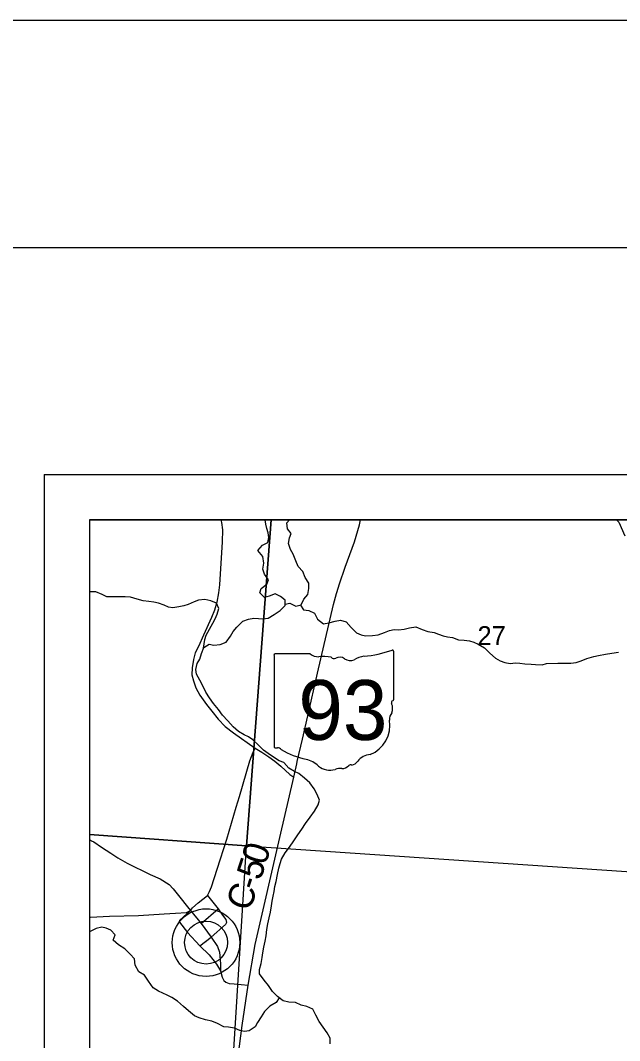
# Model space of a CAD drawing. Extents: x 0 to 34, y 0 to 22.
# Drawn here: x 1.948 to 3.268, y 19.753 to 22 of the extents above; entities that cross this region are included whole.
import ezdxf

# ---------------------------------------------------------------- set-up
doc = ezdxf.new("R2010")
doc.units = 0
for name, color, linetype in [('Default', 7, 'Continuous'), ('GM_X_County_Road', 7, 'Continuous'), ('GM_X_County_Road_Text', 7, 'Continuous'), ('GM_X_Minor_River', 7, 'Continuous'), ('GM_X_Section', 7, 'Continuous'), ('GM_X_Section_Text', 7, 'Continuous'), ('GM_X_State_Location', 7, 'Continuous'), ('GM_X_State_Route', 7, 'Continuous'), ('GM_X_State_Shield', 7, 'Continuous'), ('GM_X_Township_Road', 7, 'Continuous'), ('GM_X_Unincorporated', 7, 'Continuous'), ('GM_X_Unincorporated_Location', 7, 'Continuous'), ('SC_Scratch1', 7, 'Continuous'), ('SH_Border', 7, 'Continuous'), ('SH_Cut_Line', 7, 'Continuous'), ('SH_Data', 7, 'Continuous')]:
    doc.layers.add(name, color=color, linetype=linetype)

msp = doc.modelspace()

# ---------------------------------------------------------------- linework, layer by layer
at = {"layer": 'Default'}
for points in [[(2.4999, 20.9), (2.1, 20.9), (2.1, 20.207), (2.446, 20.1823)], [(3.5087, 20.9), (2.4999, 20.9), (2.446, 20.1823), (3.4572, 20.1141)], [(2.1, 20.207), (2.1, 19.197), (2.3543, 19.1806), (2.3838, 19.1776), (2.446, 20.1823)]]:
    msp.add_lwpolyline(points, close=True, dxfattribs=at)
at = {"layer": 'GM_X_County_Road'}
for points in [[(2.3895, 20.9), (2.391, 20.8942), (2.3933, 20.8785), (2.3924, 20.8516), (2.3866, 20.7573), (2.3841, 20.7398), (2.3804, 20.7189), (2.3751, 20.7012), (2.3689, 20.6848), (2.351, 20.6462), (2.3401, 20.6209), (2.3328, 20.6071), (2.3289, 20.593), (2.3261, 20.5744), (2.3254, 20.5592), (2.3291, 20.5454), (2.3342, 20.5305), (2.3431, 20.5144), (2.3576, 20.4937), (2.3694, 20.4787), (2.3832, 20.4615), (2.399, 20.4454), (2.4172, 20.4313), (2.4648, 20.3977), (2.48, 20.3885), (2.4952, 20.378), (2.5085, 20.3688), (2.5217, 20.3579), (2.5414, 20.3391), (2.5499, 20.3338)], [(3.2613, 20.9), (3.2658, 20.8947), (3.279, 20.8648)], [(2.3222, 20.0396), (2.3269, 20.0456), (2.3397, 20.0566), (2.3602, 20.073), (2.3645, 20.0814), (2.369, 20.0923), (2.3815, 20.1311), (2.4027, 20.1969), (2.423, 20.2677), (2.4305, 20.2911), (2.4536, 20.3697), (2.4605, 20.3887), (2.4648, 20.3977)], [(2.1, 20.025), (2.1023, 20.0253), (2.1444, 20.0271), (2.2081, 20.0292), (2.2649, 20.0327), (2.2893, 20.034), (2.3137, 20.0352), (2.3222, 20.0396), (2.3457, 20.0115), (2.3678, 19.9813), (2.3818, 19.9607), (2.3864, 19.9485), (2.3889, 19.9222), (2.3889, 19.9068), (2.3921, 19.8928), (2.3961, 19.8861), (2.4002, 19.882), (2.4076, 19.8795), (2.4186, 19.8785), (2.4499, 19.8758)]]:
    msp.add_lwpolyline(points, dxfattribs=at)
at = {"layer": 'GM_X_Minor_River'}
for points in [[(2.3518, 20.6193), (2.3639, 20.6262), (2.3738, 20.6243), (2.3878, 20.6255), (2.401, 20.6308), (2.4104, 20.6437), (2.4168, 20.654), (2.4244, 20.6639), (2.4379, 20.6772), (2.45, 20.6814), (2.4621, 20.6833), (2.472, 20.6829), (2.4822, 20.6822), (2.4939, 20.6838), (2.5072, 20.6914), (2.5204, 20.7009), (2.5313, 20.7112), (2.5309, 20.7233), (2.521, 20.7316), (2.5093, 20.7369), (2.4957, 20.7323), (2.4859, 20.7292), (2.4756, 20.7391), (2.4782, 20.7493), (2.4907, 20.7588), (2.4944, 20.7683), (2.4853, 20.7804), (2.4819, 20.7914), (2.4841, 20.8047), (2.4818, 20.8191), (2.4708, 20.8323), (2.4813, 20.8445), (2.493, 20.8506), (2.4949, 20.8612), (2.4933, 20.8714), (2.4907, 20.8813), (2.4887, 20.8908), (2.4869, 20.9)], [(2.5312, 20.7145), (2.5415, 20.7169), (2.5548, 20.7101), (2.5662, 20.7128), (2.5722, 20.7253), (2.5808, 20.7355), (2.5831, 20.7488), (2.583, 20.7606), (2.5754, 20.7731), (2.5697, 20.7863), (2.5594, 20.7973), (2.5549, 20.8102), (2.5484, 20.8246), (2.5427, 20.8352), (2.5381, 20.848), (2.5403, 20.8609), (2.5441, 20.8704), (2.5361, 20.8803), (2.5349, 20.8939), (2.5408, 20.9)], [(2.3512, 20.6175), (2.354, 20.6364), (2.3574, 20.6463), (2.3646, 20.6592), (2.3721, 20.6725), (2.377, 20.682), (2.3811, 20.6922), (2.3849, 20.7047), (2.3799, 20.7165), (2.3674, 20.7217), (2.3541, 20.7244), (2.3401, 20.7236), (2.3303, 20.7194), (2.3174, 20.714), (2.3076, 20.7106), (2.297, 20.7083), (2.2838, 20.7067), (2.2739, 20.7079), (2.2645, 20.712), (2.2523, 20.7165), (2.2417, 20.7188), (2.2311, 20.7206), (2.2182, 20.7221), (2.205, 20.7255), (2.1902, 20.7296), (2.1785, 20.7304), (2.1637, 20.7307), (2.1527, 20.7303), (2.1383, 20.7303), (2.1281, 20.7359), (2.1137, 20.742), (2.1001, 20.7419), (2.1, 20.7419)], [(2.5652, 20.7125), (2.5715, 20.7022), (2.5832, 20.7007), (2.5954, 20.6946), (2.6026, 20.6818), (2.6155, 20.6715), (2.6276, 20.6735), (2.6412, 20.6773), (2.6533, 20.6796), (2.6655, 20.6755), (2.6765, 20.6634), (2.6882, 20.6513), (2.6985, 20.6467), (2.7083, 20.6445), (2.7235, 20.6453), (2.736, 20.6472), (2.7496, 20.6522), (2.7609, 20.6567), (2.7711, 20.6587), (2.781, 20.6583), (2.7931, 20.6595), (2.8052, 20.6622), (2.8192, 20.6645), (2.8328, 20.6588), (2.8457, 20.6543), (2.8593, 20.6524), (2.8688, 20.6487), (2.879, 20.6445), (2.8885, 20.6427), (2.8995, 20.6412), (2.9131, 20.6363), (2.9256, 20.6355), (2.9374, 20.6337), (2.9469, 20.6307), (2.9563, 20.6261), (2.9704, 20.6186), (2.9821, 20.6069), (2.9943, 20.5959), (3.0049, 20.5899), (3.0148, 20.5861), (3.0265, 20.5839), (3.0382, 20.585), (3.0481, 20.5847), (3.0591, 20.5832), (3.0731, 20.5825), (3.0829, 20.5817), (3.0973, 20.581), (3.1071, 20.5841), (3.1314, 20.5849), (3.1457, 20.5845), (3.1601, 20.5849), (3.1722, 20.5861), (3.1832, 20.5895), (3.1957, 20.5949), (3.2108, 20.5995), (3.2214, 20.6018), (3.2369, 20.6045), (3.2505, 20.6064), (3.2653, 20.6091)], [(2.6302, 19.7466), (2.6302, 19.7587), (2.6233, 19.7704), (2.615, 19.7829), (2.6058, 19.7954), (2.5986, 19.8094), (2.5917, 19.8223), (2.5789, 19.8287), (2.5667, 19.8317), (2.5535, 19.8374), (2.5391, 19.8381), (2.5266, 19.8411), (2.5144, 19.8505), (2.503, 19.8615), (2.4943, 19.8747), (2.4848, 19.8865), (2.4749, 19.9001), (2.4749, 19.9103), (2.4782, 19.9229), (2.4805, 19.9361), (2.4819, 19.9467), (2.4842, 19.9589), (2.4868, 19.9722), (2.489, 19.9843), (2.4909, 19.9979), (2.4931, 20.0105), (2.4961, 20.0237), (2.4987, 20.0363), (2.5009, 20.0499), (2.5028, 20.0601), (2.505, 20.0715), (2.5065, 20.0814), (2.5084, 20.0924), (2.511, 20.1034), (2.5139, 20.1189), (2.5173, 20.133), (2.5203, 20.1432), (2.5233, 20.1531), (2.5312, 20.1667), (2.541, 20.1793), (2.5504, 20.1933), (2.5591, 20.2066), (2.5678, 20.2188), (2.576, 20.2317), (2.5862, 20.2457), (2.596, 20.2586), (2.6039, 20.2727), (2.6065, 20.2826), (2.6016, 20.295), (2.5947, 20.3075), (2.5856, 20.3208), (2.5734, 20.331), (2.5609, 20.3416), (2.5514, 20.3461), (2.5393, 20.3533), (2.5279, 20.3661), (2.5181, 20.3695), (2.5052, 20.3775), (2.4934, 20.3858), (2.4835, 20.3933), (2.4721, 20.4043), (2.4596, 20.416), (2.4501, 20.4224), (2.4406, 20.4266), (2.4281, 20.4338), (2.4164, 20.4447), (2.4046, 20.4576), (2.3932, 20.4701), (2.3841, 20.4826), (2.373, 20.4954), (2.3643, 20.5083), (2.3563, 20.5204), (2.3506, 20.5333), (2.343, 20.5473), (2.3357, 20.5602), (2.3342, 20.5704), (2.3376, 20.584), (2.3432, 20.5935), (2.3469, 20.6061), (2.3518, 20.6193)], [(2.5182, 19.8476), (2.5114, 19.8376), (2.4975, 19.8289), (2.4854, 19.8175), (2.4779, 19.8057), (2.4699, 19.7932), (2.4651, 19.7837), (2.4518, 19.7749), (2.4412, 19.7734), (2.4314, 19.776), (2.4193, 19.7805), (2.406, 19.7832), (2.3958, 19.7835), (2.3821, 19.7907), (2.3692, 19.7963), (2.3556, 19.799), (2.342, 19.8039), (2.3317, 19.808), (2.3184, 19.8193), (2.3071, 19.8288), (2.2941, 19.8405), (2.2813, 19.8484), (2.2714, 19.8534), (2.2619, 19.8575), (2.2521, 19.862), (2.2403, 19.8696), (2.2297, 19.884), (2.2213, 19.8972), (2.2084, 19.9051), (2.2004, 19.9195), (2.1992, 19.9332), (2.1893, 19.9434), (2.1776, 19.9555), (2.1643, 19.9645), (2.1521, 19.9744), (2.1563, 19.9861), (2.1472, 19.9967), (2.1369, 20.0009), (2.1274, 20.0035), (2.1146, 20), (2.1002, 19.9928), (2.1, 19.9928)]]:
    msp.add_lwpolyline(points, dxfattribs=at)
at = {"layer": 'GM_X_Section'}
msp.add_lwpolyline([(3.4572, 20.1141), (3.4007, 19.112), (3.378, 19.1131), (2.3838, 19.1776), (2.446, 20.1823)], close=True, dxfattribs=at)
at = {"layer": 'GM_X_State_Route'}
for points in [[(2.6449, 20.7401), (2.6509, 20.7589), (2.6636, 20.7959), (2.6836, 20.8519), (2.6949, 20.8889), (2.6972, 20.9)], [(2.5565, 20.3632), (2.5575, 20.3681), (2.569, 20.4173), (2.581, 20.4686), (2.6026, 20.5627), (2.6098, 20.594), (2.6376, 20.7136), (2.6443, 20.7382), (2.6449, 20.7401)], [(2.3912, 19.4446), (2.3997, 19.506), (2.4063, 19.5548), (2.4127, 19.6028), (2.4207, 19.6683), (2.4216, 19.6746), (2.4278, 19.7185), (2.4366, 19.7864), (2.4499, 19.8758), (2.465, 19.9651), (2.5191, 20.2008), (2.5499, 20.3338), (2.5565, 20.3632)]]:
    msp.add_lwpolyline(points, dxfattribs=at)
at = {"layer": 'GM_X_State_Shield'}
for p, q in [((2.5065, 20.6015), (2.5065, 20.4014)), ((2.5863, 20.605), (2.5091, 20.605)), ((2.7702, 20.5052), (2.7702, 20.6099)), ((2.7702, 20.5053), (2.7702, 20.5052))]:
    msp.add_line(p, q, dxfattribs=at)
for centre, radius, start, end in [((2.5095, 20.6019), 0.00305, 98.1301, 188.1301), ((2.6047, 20.6282), 0.0296, 231.6195, 271.1119), ((2.6763, 20.8778), 0.2796, 275.8445, 288.9065), ((2.7673, 20.6104), 0.00294, 351.8621, 97.738), ((2.6146, 20.4926), 0.1064, 80.4867, 94.9883), ((2.6387, 20.603), 0.00855, 219.7921, 297.1024), ((2.6512, 20.5799), 0.0178, 54.4667, 119.1411), ((2.6742, 20.6116), 0.0214, 233.8562, 294.8282), ((2.7119, 20.5438), 0.0563, 97.3462, 120.7689), ((2.7695, 20.4976), 0.00454, 107.944, 210.337), ((2.7406, 20.4843), 0.0273, 340.033, 23.6496), ((2.7671, 20.5048), 0.00314, 289.6038, 7.7341), ((2.7807, 20.4614), 0.0198, 136.8065, 186.9296), ((2.6919, 20.4481), 0.0699, 292.3089, 8.9858), ((2.5096, 20.401), 0.00308, 171.9584, 258.3066), ((2.51, 20.4214), 0.0235, 267.339, 280.6039), ((2.5149, 20.3899), 0.00848, 29.7484, 93.2717), ((2.6219, 20.5697), 0.2019, 240.4129, 257.1985), ((2.7214, 20.3452), 0.0383, 94.4031, 142.5768), ((2.5617, 20.3115), 0.0632, 47.1842, 75.836), ((2.63, 20.3889), 0.0401, 230.7004, 286.2918), ((2.6561, 20.3739), 0.0214, 268.777, 315.5493), ((2.6755, 20.3545), 0.00601, 65.7517, 132.6484), ((2.6729, 20.382), 0.0226, 282.8732, 323.2771), ((2.6532, 20.3197), 0.0329, 85.6951, 111.2099)]:
    msp.add_arc(centre, radius, start, end, dxfattribs=at)
at = {"layer": 'GM_X_Township_Road'}
msp.add_line((2.3457, 20.0115), (2.3836, 20.0434), dxfattribs=at)
for points in [[(2.1, 20.196), (2.1003, 20.1959), (2.1047, 20.1936)], [(2.1047, 20.1936), (2.1099, 20.191), (2.1265, 20.1792), (2.1468, 20.1662), (2.1625, 20.1557), (2.1832, 20.1439), (2.2335, 20.1193), (2.2561, 20.1096), (2.2758, 20.0972), (2.2843, 20.0874), (2.2991, 20.0696), (2.3156, 20.0483), (2.3222, 20.0396)], [(2.3602, 20.073), (2.3836, 20.0434), (2.3933, 20.0294), (2.4004, 20.02), (2.4018, 20.0135), (2.4, 20.0089)], [(2.2985, 20.0142), (2.2989, 20.0188), (2.3222, 20.0396)], [(2.2985, 20.0142), (2.3156, 19.9918), (2.3433, 19.9624), (2.3637, 19.9425), (2.3797, 19.9218), (2.3889, 19.9068)], [(2.3433, 19.9624), (2.3678, 19.9813), (2.4, 20.0089)]]:
    msp.add_lwpolyline(points, dxfattribs=at)
at = {"layer": 'GM_X_Unincorporated'}
for radius in [0.0744, 0.0472]:
    msp.add_circle((2.3568, 19.9692), radius, dxfattribs=at)
at = {"layer": 'GM_X_Unincorporated_Location'}
msp.add_line((2.3568, 19.9692), (2.3568, 19.9692), dxfattribs=at)
at = {"layer": 'SC_Scratch1'}
msp.add_lwpolyline([(5.53, 20.9), (2.1, 20.9), (2.1, 19.1982), (2.3572, 19.1804), (3.3448, 19.1146), (4.3628, 19.0495), (4.7394, 19.0241), (4.7997, 19.0196), (5.182, 18.9932), (5.4007, 18.9779), (5.4089, 19.0989), (5.4469, 19.6641), (5.4955, 20.3864)], close=True, dxfattribs=at)
at = {"layer": 'SH_Border'}
msp.add_lwpolyline([(1.5, 21.5), (33.5, 21.5), (33.5, 0.5), (1.5, 0.5)], close=True, dxfattribs=at)
at = {"layer": 'SH_Cut_Line'}
msp.add_lwpolyline([(0, 0), (34, 0), (34, 22), (0, 22)], close=True, dxfattribs=at)
at = {"layer": 'SH_Data'}
for p, q in [((2, 21), (9, 21)), ((2, 21), (2, 14)), ((2.1, 20.9), (2.1, 14.1)), ((2.1, 20.9), (8.9, 20.9))]:
    msp.add_line(p, q, dxfattribs=at)

# ---------------------------------------------------------------- texts
at = {"layer": 'GM_X_County_Road_Text'}
for s, rotation, p in [('0', 72.146, (2.4876, 20.1377)), ('5', 72.0085, (2.4767, 20.1043)), ('-', 71.6598, (2.4693, 20.0818)), ('C', 69.0045, (2.4516, 20.0355))]:
    msp.add_text(s, height=0.0568, rotation=rotation, dxfattribs=at).set_placement(p)
at = {"layer": 'GM_X_Section_Text'}
msp.add_text('27', height=0.04186, rotation=0, dxfattribs=at).set_placement((2.9548, 20.6242))
at = {"layer": 'GM_X_State_Location'}
msp.add_text('93', height=0.000189, rotation=0, dxfattribs=at).set_placement((2.5877, 20.4744))
for s in ['s', 'r']:
    msp.add_text(s, height=0.000189, dxfattribs=at).set_placement((2.6354, 20.4882))
at = {"layer": 'GM_X_State_Shield'}
msp.add_text('93', height=0.13184, dxfattribs=at).set_placement((2.5602, 20.4155))

doc.saveas('drawing.dxf')
